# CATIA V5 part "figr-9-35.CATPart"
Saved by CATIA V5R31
Part number: Part1
Bounding box of the stored display mesh (mm): x -250 to 0, y -60 to 60, z 0 to 100
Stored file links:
  D:\PROJECTS\Project 2021\US EDITION\CATIA V5 6R 2021\Resources\Part Files\c09_catia_v5_6r2021_prt\c09_catia_v5_6r2021_prt\figr-9-35.CATPart
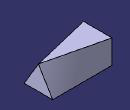
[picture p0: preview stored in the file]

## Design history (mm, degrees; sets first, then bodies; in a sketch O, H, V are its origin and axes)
Body1 (main body)
  Sketch1 on yz-plane, origin (0, 0, 0), H (0, 1, 0), V (0, 0, 1)
    point P1 (-60, 0)
    line L1 (-60, 0) -> (0, 100)
    point P2 (0, 100)
    line L2 (0, 100) -> (60, 0)
    point P3 (60, 0)
    line L3 (60, 0) -> (-60, 0)
    coincidence: P1 H, P2 V, P3 H
    horizontal: L3 H
    midpoint: O L3
  Sketch2, origin (-250, 0, 0), H (0, 1, 0), V (0, 0, 1)
    point P1 (-60, 0)
    line L1 (-60, 0) -> (60, 0)
    line L2 (60, 0) -> (60, 100)
    line L3 (60, 100) -> (-60, 100)
    line L4 (-60, 100) -> (-60, 0)
    coincidence: P1 H
    horizontal: L1 H, L3 H
    vertical: L2 V, L4 V
  Loft1: Sections (Sketch1; Sketch2), SectionCouplingPoints ({coupling CouplingPoints (vertex [element of Sketch1 | element of Sketch1]; vertex [element of Sketch2 | element of Sketch2])}; {coupling CouplingPoints (vertex [element of Sketch1 | element of Sketch1]; vertex [element of Sketch2 | element of Sketch2])}; {coupling CouplingPoints (vertex [element of Sketch1 | element of Sketch1]; vertex [element of Sketch2 | element of Sketch2])})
